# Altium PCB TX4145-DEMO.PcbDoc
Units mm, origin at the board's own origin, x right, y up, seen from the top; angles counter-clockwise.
Board outline 53.34 x 40.51 mm, 2 copper layers (Top Layer, Bottom Layer); 22 components, 10 nets, 62 pads, 65 vias.
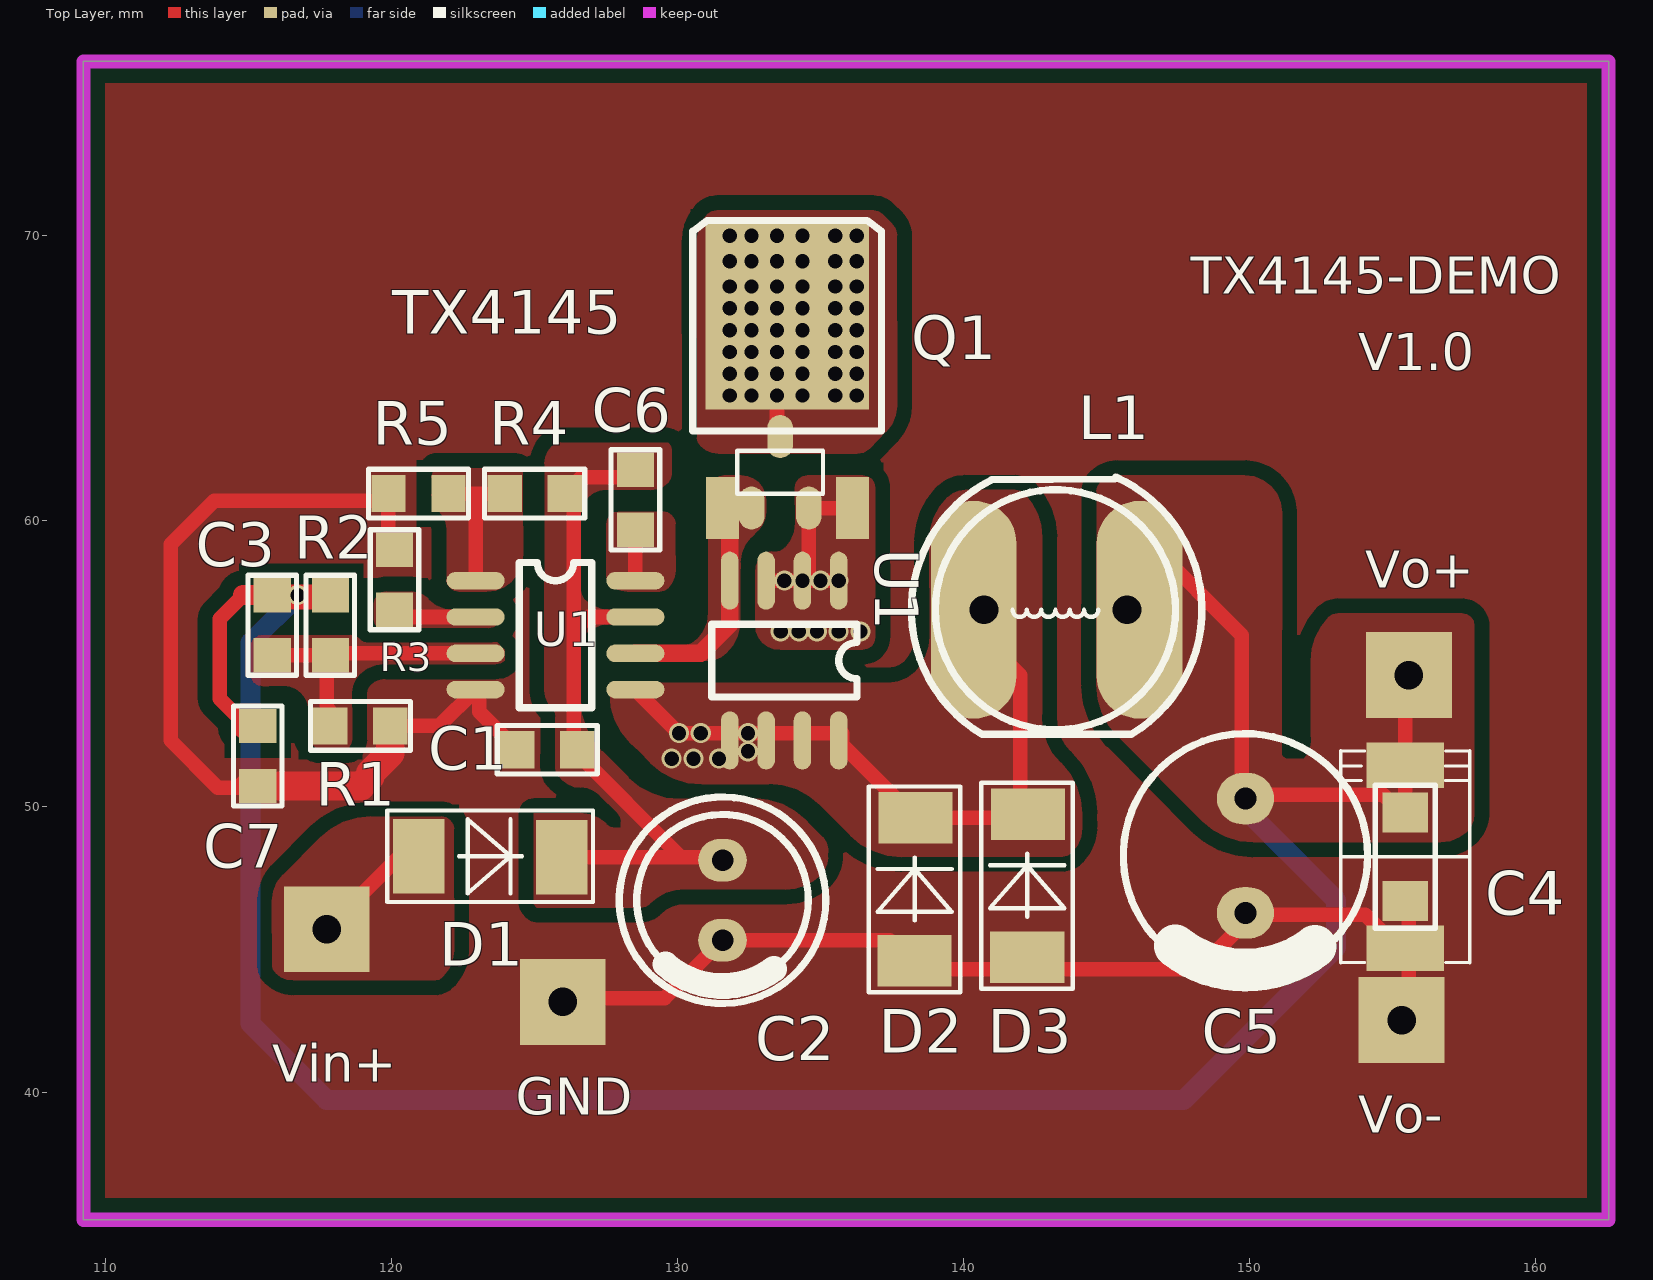
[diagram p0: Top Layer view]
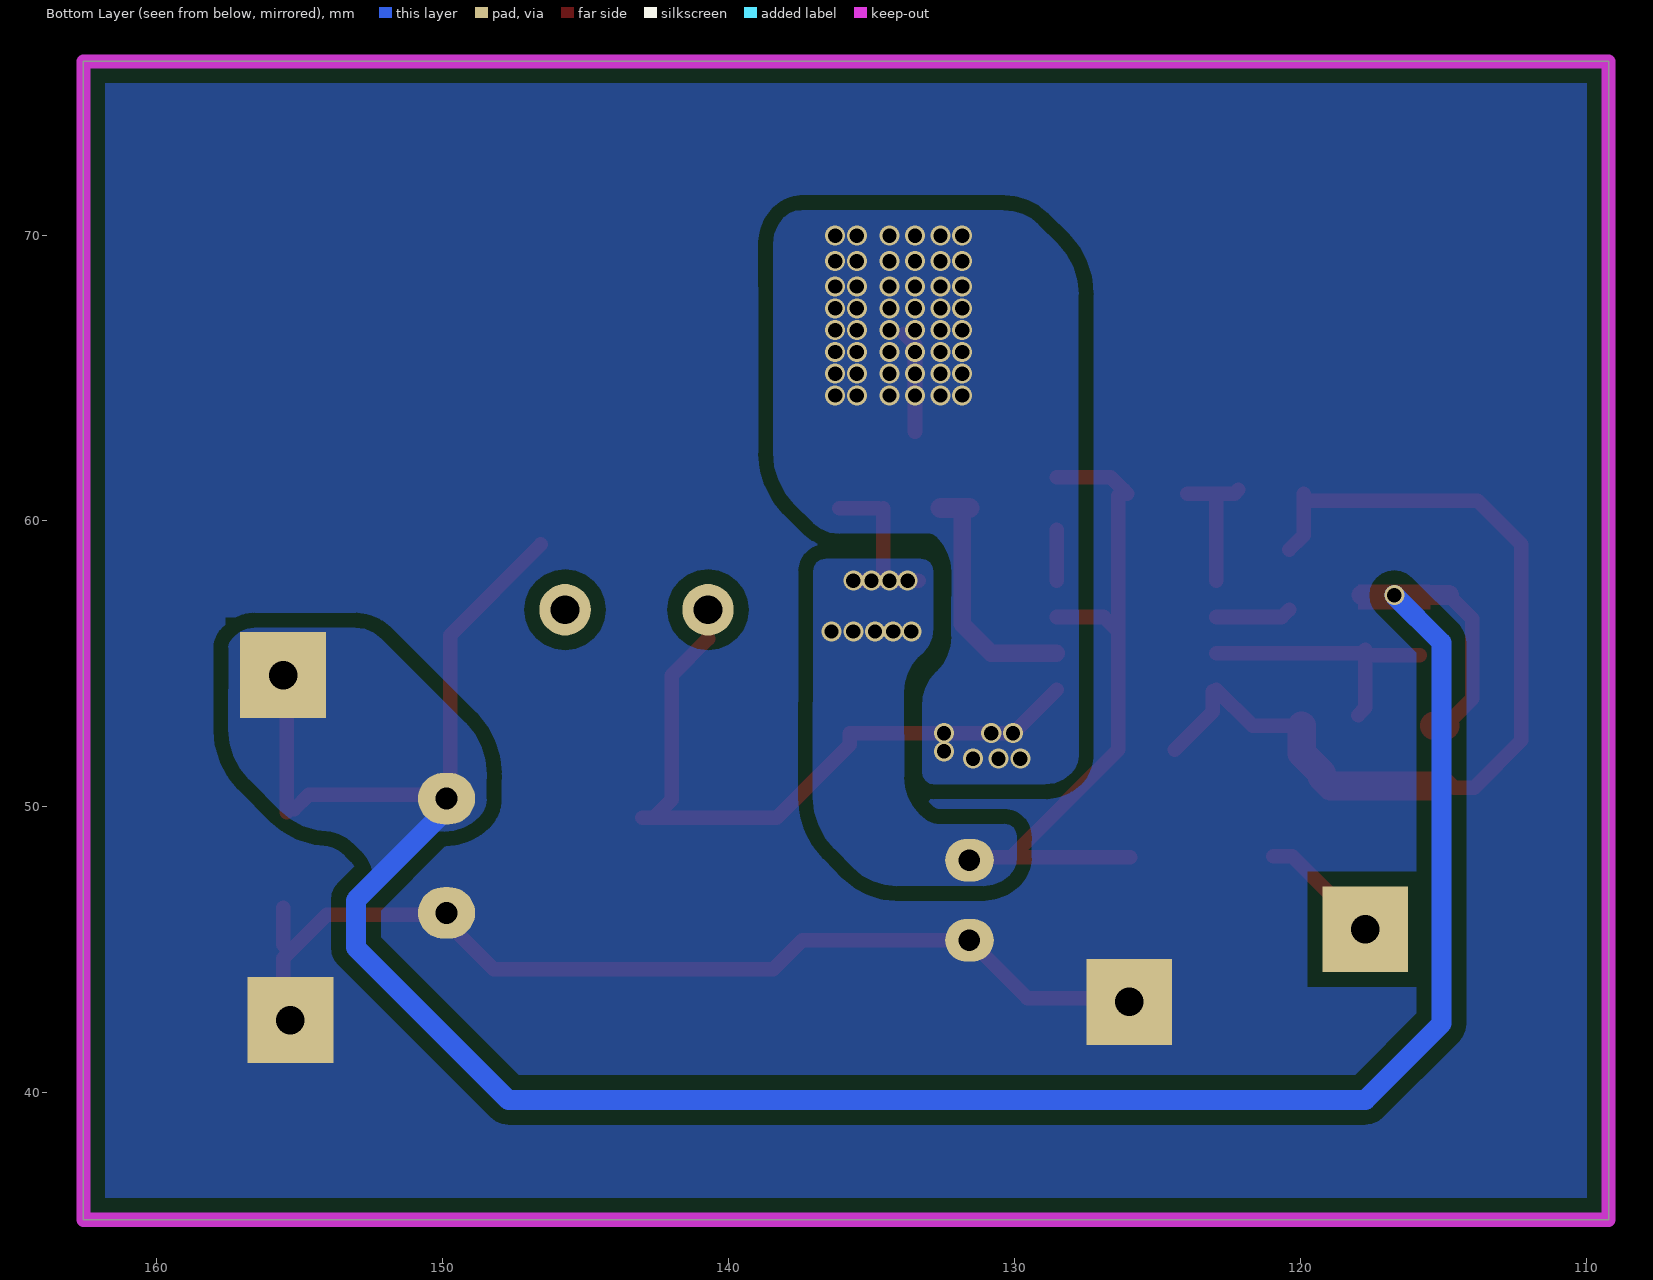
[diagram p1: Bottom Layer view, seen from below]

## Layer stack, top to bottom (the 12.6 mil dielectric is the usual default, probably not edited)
Top Layer: signal copper 0.0356
Dielectric: dielectric 0.32, FR-4, Dk 4.8
Bottom Layer: signal copper 0.0356

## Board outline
109.22,35.56 162.56,35.56 162.56,76.073 109.22,76.073

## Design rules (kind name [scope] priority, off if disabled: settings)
Clearance [All] p1: gap=0.508
ComponentClearance [All] p1 off: gap=0.254 collisioncheckmode=3 verticalgap=0.254 showdistances=FALSE
Height [All] p1 off: minheight=0 maxheight=25.4 prefheight=12.7
PlaneConnect [All] p1: planeconnectstyle=Direct reliefexpansion=0.508 reliefentries=4 reliefconductorwidth=0.254 reliefairgap=0.254
PolygonConnect [All] p1: connectstyle=Direct reliefconductorwidth=0.254 reliefentries=4 polygonreliefangle="90 Angle"
RoutingVias [All] p1: holewidth=0.711 width=1.27 viastyle="Through Hole" minholewidth=0.711 minwidth=1.27 maxholewidth=0.711 maxwidth=1.27
SilkscreenOverComponentPads SilkToSolderMaskClearance [IsPad] p1: minsilkscreentomaskgap=0.254
SolderMaskExpansion [All] p1: expansion=0.102
TestPointUsage [All] p1: valid=0 allowmultiple=FALSE
Testpoint [All] p1: side=3 testpointundercomponent=TRUE minsize=1.016 maxsize=2.54 preferedsize=1.524 minholesize=0 maxholesize=1.016 preferedholesize=0.813 testpointgrid=0.025 style=297 order=0123456789
Width [All] p1: maxlimit=5.08 minlimit=0.508 preferedwidth=0.508
20 further rules are at their usual default settings.

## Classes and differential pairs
component class OC5823-0902原理图: C1 C2 C3 C4 C5 C6 D1 D2 D3 L1 Q1 R1 R2 R3 R4 R5 U1

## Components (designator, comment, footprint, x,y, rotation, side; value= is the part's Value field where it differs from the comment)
C1 "CAP" 0805R 126.492,52 r180 top
C2 "" c6*12 131.572,46.736 r270 top
C3 "" 0805R 115.824,57.404 r270 top
C4 "" 1206R 155.448,48.26 r90 top
C5 "" C8*12 149.86,50.292 r180 top
C6 "" 0805R 128.524,59.69 r90 top
C7 "" 0805R 115.316,52.832 r270 top (schematic designator C4)
D1 "DIODE" SMB 123.444,48.26 r0 top
D2 "" SMB 138.303,47.117 r90 top
D3 "" SMB 142.24,47.244 r90 top
L1 "" CD105 143.256,56.896 r90 top
Q1 "MOSFET P" TO252 131.572,60.452 r0 top
R1 "" 0805R 117.856,57.404 r270 top
R2 "" 0805R 117.856,52.832 r0 top
R3 "" 0805R 120.1,56.896 r90 top
R4 "" 0805R 123.952,60.96 r0 top
R5 "" 0805R 119.888,60.96 r0 top
U1 "TX4145" SO-8 135.636,57.912 r270 top
U1 "TX4145" SO-8 122.936,57.912 r0 top
? "Comment" L8*10 140.716,56.896 r0 top
? "Comment" 7343 155.448,48.26 r0 top
? "Comment" SOT23-3 132.588,60.452 r0 top

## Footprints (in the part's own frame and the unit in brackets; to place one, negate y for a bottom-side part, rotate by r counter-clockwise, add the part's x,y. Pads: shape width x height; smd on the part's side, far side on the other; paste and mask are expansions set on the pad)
0805R [mm]
  rect 1.2x1.3 smd: 1(0,0) 2(2.1,0)
  silkscreen extent -0.7,-0.85 2.8,0.85
1206R [mm]
  rect 1.4x1.6 smd: 1(1.55,0) 2(-1.55,0)
  silkscreen extent -2.5,-1.05 2.5,1.05
7343 [mm]
  rect 2.7x1.6 smd: 1(0,3.2) 2(0,-3.2)
  silkscreen extent -2.25,-3.7 2.25,3.7
c6*12 [mm]
  oval 1.5x1.7 hole 0.75: 1(-1.4,0) 2(1.4,0)
  silkscreen extent -3.61,-3.61 3.61,3.61
C8*12 [mm]
  oval 2x1.8 hole 0.762: 1(0,0) 2(0,4)
  silkscreen extent -4.27,-2.27 4.27,6.27
CD105 [mm]
  oval 7.62x3 smd: 1(0,-2.9) 2(0,2.9)
  silkscreen extent -4.36,-5.08 4.64,5.08
L8*10 [mm]
  round 1.8 hole 1: 1(0,0) 2(5,0)
  silkscreen extent -1.7,-4.2 6.7,4.2
SMB [mm]
  rect 1.8x2.6 smd: 1(-2.5,0.016) 2(2.5,-0.016)
  silkscreen extent -3.6,-1.58 3.6,1.62
SO-8 [mil]
  oval 80x24 smd: 1(0,0) 2(0,-50) 3(0,-100) 4(0,-150) 5(220,-150) 6(220,-100) 7(220,-50) 8(220,0)
  silkscreen extent 60,-175 160,25
SOT23-3 [mm]
  oval 0.9x1.5 smd: 1(0,0) 2(1,2.5) 3(2,0)
  silkscreen extent -0.5,0.5 2.5,2
TO252 [mil]
  rect 45x85 smd: 1(0,0) 3(179,0)
  rect 225x255.91 smd: 2(89,263.78)
  silkscreen extent -41,106 219,396

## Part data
C1: "Capacitor"
C2 C5: library part CAPACITOR, "Capacitor"
C3 C4 C6 C7: library part CAP, "Capacitor"
D1: "Diode"
D2 D3: library part DIODE, "Diode"
L1: library part INDUCTOR
R1 R2 R3 R4 R5: library part RES1_1
U1: library part "HEADER 4X2"

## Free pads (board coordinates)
  rect 3x3 hole 1: 0(155.321,42.545) 1(155.575,54.61) 2(117.729,45.72) 3(125.984,43.18)

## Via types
v1: diameter 0.7, hole 0.5, Top Layer to Bottom Layer, 65 vias

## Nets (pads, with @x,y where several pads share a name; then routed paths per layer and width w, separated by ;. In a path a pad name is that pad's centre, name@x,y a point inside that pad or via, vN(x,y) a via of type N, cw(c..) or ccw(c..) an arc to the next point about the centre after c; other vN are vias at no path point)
GND: ?.2@155.448,45.06 C1.2 C2.2 C4.2 C5.2 C7.2 D2.1 D3.1 pad.0 pad.3 R2.2 R3.2 R5.1 U1.4@122.936,54.102 | length 69.3
  Top Layer w0.508: C7.2@115.443,50.732 C7.2 114.994,51.054 114.613,50.673 113.919,50.673 112.268,52.324 112.268,59.182 113.792,60.706 R5.1@119.888,60.706 ; R5.1 119.888,59.504 R3.2@120.396,58.996 ; R2.2 121.666,52.832 122.936,54.102 123.063,54.049 123.063,53.329 C1.2 ; pad.3@126.492,43.307 129.543,43.307 C2.2 137.417,45.336 138.43,44.323 148.209,44.323 150.114,46.228 154.051,46.228 155.575,44.704 155.575,42.799 pad.0 ; ?.2@155.448,45.06 155.575,45.187 C4.2@155.575,46.482
  Top Layer w1: C7.2 118.931,50.732 119.253,51.054 119.253,51.174 119.956,51.877 R2.2
NetC1_1: ?.3 C1.1 C2.1 C6.2 D1.2 Q1.3 R4.2 U1.1@135.636,57.912 U1.2@134.366,57.912 U1.3@133.096,57.912 U1.7@128.524,56.642 | length 31.3
  Top Layer w0.508: D1.2 131.464,48.244 C2.1 ; R4.2 126.628,61.536 C6.2@128.524,61.536 ; R4.2@126.166,61.074 126.365,60.875 126.365,52 130.121,48.244 ; 126.492,56.261 126.873,56.642 U1.7@128.524,56.642 ; U1.3@133.35,57.912 v1(135.636,57.912) ; v1(134.366,57.912) 134.588,58.134 ?.3 ; ?.3@134.747,60.452 Q1.3
  other v1: 133.604,56.134 134.239,56.134 134.874,56.134 135.636,56.134 136.398,56.134 133.731,57.912 135.001,57.912
NetC3_1: ?.1@155.448,51.46 ?.2@145.716,56.896 C3.1 C4.1 C5.1 C7.1 L1.1 pad.1 R1.1 | length 92.6
  Top Layer w0.508: 114.808,57.404 113.988,56.584 113.988,53.779 C7.1@114.935,52.832 ; L1.1@146.558,59.182 149.733,56.007 149.733,50.419 154.686,50.419 C4.1@155.194,49.911 ; C4.1 155.448,54.483 pad.1
  Top Layer w0.7: 114.808,57.404 R1.1
  Top Layer w1: C7.1@114.935,52.832 C7.1
  Bottom Layer w0.7: v1(116.713,57.404) 115.062,55.753 115.062,42.418 117.729,39.751 147.701,39.751 153.035,45.085 153.035,46.736 C5.1@149.733,50.038
NetC3_2: C3.2 R1.2 R2.1 U1.3@122.936,55.372 | length 9.7
  Top Layer w0.508: C3.2 117.788,55.304 R1.2@117.856,55.372 ; R2.1@117.983,53.213 117.729,53.467 117.729,55.499 R1.2@117.856,55.372 ; U1.3@122.936,55.372 R1.2@117.856,55.372
NetC6_1: C6.1 U1.8@128.524,57.912 | length 1.8
  Top Layer w0.508: U1.8@128.524,57.912 C6.1
NetD2_2: ?.1@140.716,56.896 ?.2@133.588,62.952 D2.2 D3.2 L1.2 Q1.2 U1.5 U1.6@133.096,52.324 U1.7@134.366,52.324 U1.8@135.636,52.324 | length 27.2
  Top Layer w0.508: U1.5@128.524,54.102 v1(130.048,52.578) 135.763,52.578 135.763,52.173 D2.2 D3.2@143.018,49.617 ; ?.2@133.477,63.119 133.477,66.167 Q1.2@133.858,66.548 ; L1.2@140.716,55.88 141.986,54.61 141.986,50.252 D3.2@142.621,49.617
  other v1: 129.794,51.689 130.556,51.689 131.445,51.689 132.461,51.943 130.81,52.578 132.461,52.578 131.826,64.389 132.588,64.389 133.477,64.389 134.366,64.389 135.509,64.389 136.271,64.389 131.826,65.151 132.588,65.151 133.477,65.151 134.366,65.151 135.509,65.151 136.271,65.151 131.826,65.913 132.588,65.913 133.477,65.913 134.366,65.913 135.509,65.913 136.271,65.913 131.826,66.675 132.588,66.675 133.477,66.675 134.366,66.675 135.509,66.675 136.271,66.675 131.826,67.437 132.588,67.437 133.477,67.437 134.366,67.437 135.509,67.437 136.271,67.437 131.826,68.199 132.588,68.199 133.477,68.199 134.366,68.199 135.509,68.199 136.271,68.199 131.826,69.088 132.588,69.088 133.477,69.088 134.366,69.088 135.509,69.088 136.271,69.088 131.826,69.977 132.588,69.977 133.477,69.977 134.366,69.977 135.509,69.977 136.271,69.977
NetOC5823_1: R4.1 R5.2 U1.1@122.936,57.912 | length 4.9
  Top Layer w0.508: R5.2@122.174,61.087 122.301,60.96 R4.1 ; U1.1@122.936,57.912 122.936,60.833 123.063,60.96
NetOC5823_2: R3.1 U1.2@122.936,56.642 | length 2.6
  Top Layer w0.508: R3.1@120.396,56.896 120.65,56.642 U1.2@122.936,56.642
NetOC5823_6: ?.1@132.588,60.452 Q1.1 U1.4@131.826,57.912 U1.6@128.524,55.372 | length 8.5
  Top Layer w0.6: U1.6@128.524,55.372 130.81,55.372 131.826,56.388 Q1.1@131.826,60.198
  Top Layer w0.7: Q1.1 ?.1@132.588,60.452
VCC: D1.1 pad.2 | length 4.3
  Top Layer w0.508: pad.2 120.285,48.276 D1.1

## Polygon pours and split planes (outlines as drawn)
GND on Top Layer "Top Layer-No Net" (solid, remove dead copper, pour order 1011): 109.22,35.306 161.027,35.306 ccw(c161.027,37.474) 162.56,35.941 162.56,74.847 ccw(c160.826,74.847) 162.052,76.073 110.446,76.073 ccw(c110.446,74.339) 109.22,75.565 109.22,35.56
NetD2_2 on Top Layer "Top Layer-No Net" (solid, remove dead copper, pour order 1010): 130.683,62.992 130.683,69.819 cw(c131.984,69.819) 131.064,70.739 cw(c131.371,70.432) 131.371,70.866 132.207,70.866 136.853,70.866 cw(c136.853,70.432) 137.16,70.739 137.488,70.411 cw(c137.055,69.977) 137.668,69.977 137.668,64.039 cw(c136.367,64.039) 137.287,63.119 136.705,62.537 cw(c136.271,62.97) 136.271,62.357 131.423,62.357 cw(c131.423,63.224) 130.81,62.611 cw(c131.117,62.918) 130.683,62.918 130.683,62.992
NetC3_2 on Top Layer "Top Layer-No Net" (solid, remove dead copper, pour order 1009): 123.698,55.753 119.179,55.753 cw(c119.179,56.187) 118.872,55.88 ccw(c118.565,55.573) 118.565,56.007 117.856,56.007 115.496,56.007 ccw(c115.496,55.573) 115.189,55.88 ccw(c115.496,55.573) 115.062,55.573 115.062,55.118 115.062,54.663 ccw(c115.496,54.663) 115.189,54.356 ccw(c115.496,54.663) 115.496,54.229 115.697,54.229 116.227,54.229 cw(c116.227,53.362) 116.84,53.975 cw(c116.227,53.362) 117.094,53.362 117.094,52.451 ccw(c117.401,52.451) 117.184,52.234 117.348,52.07 118.491,52.07 ccw(c118.184,52.377) 118.618,52.377 118.618,52.959 118.618,53.997 cw(c119.485,53.997) 118.872,54.61 cw(c119.792,53.69) 119.792,54.991 123.19,54.991 123.645,54.991 ccw(c123.645,55.425) 123.952,55.118 123.952,55.499 123.698,55.753
NetOC5823_2 on Top Layer "Top Layer-No Net" (solid, remove dead copper, pour order 1008): 123.571,56.896 122.205,56.896 cw(c122.205,58.197) 121.285,57.277 ccw(c120.672,56.664) 120.672,57.531 120.523,57.531 119.814,57.531 ccw(c119.814,57.097) 119.507,57.404 ccw(c119.814,57.097) 119.38,57.097 119.38,56.896 119.38,56.568 ccw(c119.814,56.568) 119.507,56.261 123.391,56.261 ccw(c123.391,56.695) 123.698,56.388 123.698,56.589 ccw(c123.264,56.589) 123.571,56.896
NetC3_1 on Top Layer "Top Layer-No Net" (solid, remove dead copper, pour order 1007): 144.653,59.944 144.653,54.265 ccw(c147.193,54.265) 145.397,52.469 145.415,52.451 148.354,49.512 ccw(c150.15,51.308) 150.15,48.768 153.289,48.768 156.687,48.768 ccw(c156.687,50.069) 157.607,49.149 ccw(c156.994,49.762) 157.861,49.762 157.861,52.197 157.861,56.335 ccw(c157.427,56.335) 157.734,56.642 ccw(c157.427,56.335) 157.427,56.769 156.591,56.769 153.088,56.769 ccw(c153.088,56.335) 152.781,56.642 ccw(c154.314,55.109) 152.146,55.109 152.146,52.578 152.146,52.302 cw(c151.279,52.302) 151.892,51.689 151.384,51.689 cw(c151.384,51.996) 151.167,51.779 151.13,51.816 151.13,52.07 151.13,60.294 ccw(c149.829,60.294) 150.749,61.214 ccw(c149.829,60.294) 149.829,61.595 146.939,61.595 145.393,61.595 ccw(c145.393,60.728) 144.78,61.341 ccw(c145.087,61.034) 144.653,61.034 144.653,60.325 144.653,59.69
NetOC5823_1 on Top Layer "Top Layer-No Net" (solid, remove dead copper, pour order 1006): 121.539,61.849 124.28,61.849 cw(c124.28,61.415) 124.587,61.722 124.587,60.833 124.587,58.832 cw(c123.286,58.832) 124.206,57.912 124.184,57.89 cw(c123.317,58.757) 123.317,57.531 122.354,57.531 cw(c122.354,57.965) 122.047,57.658 cw(c122.354,57.965) 121.92,57.965 121.92,58.674 121.92,59.712 ccw(c121.053,59.712) 121.666,60.325 cw(c122.279,60.938) 121.412,60.938 121.412,61.468 121.412,61.542 cw(c121.846,61.542) 121.539,61.849
NetC1_1 on Top Layer "Top Layer-No Net" (solid, remove dead copper, pour order 1005): 129.159,62.738 125.91,62.738 ccw(c125.91,62.304) 125.603,62.611 ccw(c126.216,61.998) 125.349,61.998 125.349,61.976 125.349,54.08 ccw(c126.216,54.08) 125.603,53.467 cw(c125.296,53.16) 125.73,53.16 125.73,52.324 125.73,51.361 ccw(c126.164,51.361) 125.857,51.054 125.969,50.942 ccw(c126.619,51.593) 126.619,50.673 cw(c126.619,49.753) 127.269,50.404 127.889,49.784 cw(c127.582,49.477) 128.016,49.477 128.016,49.276 127.815,49.276 cw(c127.815,49.71) 127.508,49.403 ccw(c126.588,48.483) 126.588,49.784 124.968,49.784 124.767,49.784 ccw(c124.767,49.35) 124.46,49.657 ccw(c125.073,49.044) 124.206,49.044 124.206,48.006 124.206,47.349 ccw(c125.073,47.349) 124.46,46.736 ccw(c125.073,47.349) 125.073,46.482 127.381,46.482 128.725,46.482 ccw(c128.725,46.916) 129.032,46.609 cw(c130.258,45.383) 130.258,47.117 132.08,47.117 133.775,47.117 ccw(c133.775,48.851) 135.001,47.625 ccw(c134.388,48.238) 135.255,48.238 135.255,48.514 ccw(c134.642,48.514) 135.075,48.948 134.62,49.403 134.475,49.548 ccw(c132.679,47.752) 132.679,50.292 130.937,50.292 130.084,50.292 cw(c130.084,52.832) 128.288,51.036 127.381,51.943 127.363,51.961 cw(c129.159,53.757) 126.619,53.757 126.619,54.229 126.619,55.7 cw(c127.053,55.7) 126.746,56.007 cw(c127.666,55.087) 127.666,56.388 127.889,56.388 128.927,56.388 ccw(c128.927,57.255) 129.54,56.642 129.466,56.716 ccw(c129.032,56.283) 129.032,56.896 127.666,56.896 cw(c127.666,58.197) 126.746,57.277 cw(c127.053,57.584) 126.619,57.584 126.619,57.912 126.619,60.22 cw(c127.486,60.22) 126.873,60.833 cw(c127.486,60.22) 127.486,61.087 128.27,61.087 129.054,61.087 ccw(c129.054,61.954) 129.667,61.341 ccw(c129.36,61.648) 129.794,61.648 129.794,62.103 129.794,62.484 ccw(c129.487,62.484) 129.704,62.701 129.667,62.738 129.159,62.738
NetC6_1 on Top Layer "Top Layer-No Net" (solid, remove dead copper, pour order 1004): 128.397,60.325 129.487,60.325 cw(c129.487,59.891) 129.794,60.198 cw(c129.487,59.891) 129.921,59.891 129.921,59.309 129.921,58.271 cw(c129.054,58.271) 129.667,57.658 cw(c129.36,57.965) 129.36,57.531 128.651,57.531 128.248,57.531 cw(c128.248,58.398) 127.635,57.785 cw(c127.942,58.092) 127.508,58.092 127.508,58.547 127.508,59.891 cw(c127.942,59.891) 127.635,60.198 cw(c127.942,59.891) 127.942,60.325 128.397,60.325
NetOC5823_6 on Top Layer "Top Layer-No Net" (solid, remove dead copper, pour order 1003): 128.397,55.626 130.07,55.626 ccw(c130.07,56.493) 130.683,55.88 ccw(c129.763,56.8) 131.064,56.8 131.064,58.674 131.064,60.855 cw(c131.931,60.855) 131.318,61.468 cw(c131.625,61.161) 131.625,61.595 131.826,61.595 132.229,61.595 cw(c132.229,60.728) 132.842,61.341 cw(c132.229,60.728) 133.096,60.728 133.096,60.325 cw(c132.176,60.325) 132.827,59.675 132.588,59.436 132.566,59.414 ccw(c133.433,58.547) 132.207,58.547 132.207,56.598 cw(c130.473,56.598) 131.699,55.372 cw(c131.086,55.985) 131.086,55.118 130.683,55.118 128.883,55.118 cw(c128.883,55.985) 128.27,55.372 cw(c128.577,55.372) 128.36,55.589 128.397,55.626
NetD2_2 on Top Layer "Top Layer-No Net" (solid, remove dead copper, pour order 1002): 128.778,54.356 137.383,54.356 ccw(c137.383,55.657) 138.303,54.737 ccw(c137.077,55.963) 138.811,55.963 138.811,56.007 138.811,59.3 cw(c140.979,59.3) 139.446,60.833 cw(c140.059,60.22) 140.059,61.087 140.081,61.087 141.806,61.087 cw(c141.806,60.653) 142.113,60.96 cw(c140.58,59.427) 142.748,59.427 142.748,53.34 142.748,53.095 ccw(c144.916,53.095) 143.383,51.562 143.401,51.544 cw(c141.605,49.748) 144.145,49.748 144.145,49.276 cw(c142.919,49.276) 143.786,48.409 143.764,48.387 cw(c143.457,48.694) 143.457,48.26 139.319,48.26 137.831,48.26 cw(c137.831,50.8) 136.035,49.004 136.017,49.022 134.983,50.056 ccw(c133.187,48.26) 133.187,50.8 131.318,50.8 130.846,50.8 cw(c130.846,53.34) 129.05,51.544 128.651,51.943 128.353,52.241 cw(c130.088,53.975) 127.635,53.975 cw(c127.942,53.975) 127.725,54.192 127.762,54.229 cw(c128.069,53.922) 128.069,54.356 128.778,54.356
NetC1_1 on Top Layer "Top Layer-No Net" (solid, remove dead copper, pour order 1001): 134.747,61.595 136.472,61.595 cw(c136.472,61.161) 136.779,61.468 cw(c136.472,61.161) 136.906,61.161 136.906,61.087 136.906,55.933 cw(c136.472,55.933) 136.779,55.626 cw(c136.472,55.933) 136.472,55.499 135.001,55.499 133.582,55.499 cw(c133.582,56.366) 132.969,55.753 cw(c133.582,56.366) 132.715,56.366 132.715,56.896 132.715,58.188 cw(c133.582,58.188) 132.969,58.801 cw(c133.276,58.494) 133.276,58.928 133.35,58.928 133.424,58.928 ccw(c133.424,59.362) 133.731,59.055 133.753,59.077 ccw(c132.886,59.944) 134.112,59.944 134.112,61.161 cw(c134.546,61.161) 134.239,61.468 cw(c134.546,61.161) 134.546,61.595 134.747,61.595
VCC on Top Layer "Top Layer-No Net" (solid, remove dead copper, pour order 1000): 120.396,49.657 121.74,49.657 cw(c121.74,49.223) 122.047,49.53 cw(c121.74,49.223) 122.174,49.223 122.174,48.641 122.174,44.989 cw(c120.873,44.989) 121.793,44.069 121.756,44.032 cw(c121.539,44.249) 121.539,43.942 116.564,43.942 cw(c116.564,44.809) 115.951,44.196 115.914,44.233 cw(c116.131,44.45) 115.824,44.45 115.824,46.705 cw(c117.125,46.705) 116.205,47.625 117.493,48.913 cw(c119.289,47.117) 119.289,49.657 120.396,49.657
GND on Bottom Layer "Top Layer-No Net" (solid, remove dead copper, pour order 1016): 109.22,35.56 161.64,35.56 ccw(c161.64,36.861) 162.56,35.941 162.56,76.073 110.446,76.073 ccw(c110.446,74.339) 109.22,75.565 109.22,35.56
NetC3_1 on Bottom Layer "Top Layer-No Net" (solid, remove dead copper, pour order 1015): 152.4,47.371 cw(c153.933,47.371) 152.849,48.455 153.035,48.641 153.074,48.68 cw(c154.267,47.486) 154.267,49.174 154.267,49.842 cw(c155.263,49.842) 154.559,50.546 ccw(c153.333,49.32) 153.333,51.054 149.606,51.054 ccw(c151.752,51.054) 150.235,49.536 150.921,48.85 152.446,47.325
NetC3_1 on Bottom Layer "Top Layer-No Net" (solid, remove dead copper, pour order 1014): 148.463,50.8 148.463,51.145 cw(c151.003,51.145) 149.207,52.941 152.146,55.88 cw(c153.066,54.96) 153.066,56.261 156.591,56.261 cw(c156.591,55.341) 157.241,55.992 157.353,55.88 cw(c157.046,55.573) 157.48,55.573 157.48,52.705 cw(c155.027,52.705) 156.762,50.971 156.718,50.927 155.684,49.893 cw(c153.888,51.689) 153.888,49.149 151.003,49.149 149.943,49.149 cw(c149.943,50.883) 148.717,49.657 cw(c149.33,50.27) 148.463,50.27 148.463,50.8
NetD2_2 on Bottom Layer "Top Layer-No Net" (solid, remove dead copper, pour order 1013): 133.223,51.435 133.223,53.511 ccw(c131.489,53.511) 132.715,54.737 cw(c133.941,55.963) 132.207,55.963 132.207,56.515 132.207,58.21 cw(c133.941,58.21) 132.715,59.436 cw(c133.022,59.129) 133.022,59.563 135.382,59.563 136.113,59.563 ccw(c136.113,60.864) 137.033,59.944 137.686,60.597 ccw(c135.89,62.393) 138.43,62.393 138.43,66.675 138.43,69.692 ccw(c137.129,69.692) 138.049,70.612 ccw(c137.436,69.999) 137.436,70.866 136.525,70.866 130.385,70.866 ccw(c130.385,69.132) 129.159,70.358 128.506,69.705 ccw(c130.302,67.909) 127.762,67.909 127.762,61.976 127.762,51.794 ccw(c128.629,51.794) 128.016,51.181 ccw(c128.936,52.101) 128.936,50.8 129.413,50.8 132.842,50.8 ccw(c132.842,51.107) 133.059,50.89 133.096,50.927 ccw(c132.789,51.234) 133.223,51.234 133.223,51.435
NetC1_1 on Bottom Layer "Top Layer-No Net" (solid, remove dead copper, pour order 1012): 130.429,49.403 132.61,49.403 ccw(c132.61,50.27) 133.223,49.657 133.319,49.753 ccw(c132.018,51.054) 133.858,51.054 133.858,54.019 ccw(c132.124,54.019) 133.35,55.245 133.201,55.394 cw(c134.068,56.261) 132.842,56.261 132.842,58.24 cw(c133.276,58.24) 132.969,58.547 cw(c133.276,58.24) 133.276,58.674 133.731,58.674 136.599,58.674 cw(c136.599,58.24) 136.906,58.547 cw(c136.599,58.24) 137.033,58.24 137.033,57.023 137.033,50.328 cw(c134.493,50.328) 136.289,48.532 135.636,47.879 cw(c134.103,49.412) 134.103,47.244 131.572,47.244 131.095,47.244 cw(c131.095,48.545) 130.175,47.625 cw(c130.788,48.238) 129.921,48.238 129.921,48.641 129.921,48.969 cw(c130.355,48.969) 130.048,49.276 cw(c130.355,48.969) 130.355,49.403 130.429,49.403

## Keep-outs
Keep-Out Layer:
  the board outline again, w0.5

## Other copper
Top Layer:
  rectangle net NetC3_1: 115.443,56.896 117.983,57.785

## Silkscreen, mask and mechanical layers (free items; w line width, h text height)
Top Overlay:
  text "TX4145-DEMO" at 147.955,67.945 h1.3
  text "V1.0" at 153.797,65.278 h1.3
  text "Vo+" at 154.051,57.658 h1.3
  text "Vin+" at 115.824,40.386 h1.3
  text "GND" at 124.333,39.243 h1.3
  text "Vo-" at 153.797,38.608 h1.3
Bottom Solder:
  region: 129.921,70.231 128.734,69.044 ccw(c130.469,67.31) 128.016,67.31 128.016,52.995 ccw(c130.556,52.995) 128.76,51.199 128.778,51.181 ccw(c129.085,51.488) 129.085,51.054 131.953,51.054 ccw(c131.953,52.28) 132.82,51.413 132.842,51.435 ccw(c132.535,51.742) 132.969,51.742 132.969,53.467 ccw(c132.049,53.467) 132.7,54.117 131.953,54.864 cw(c132.566,55.477) 131.699,55.477 131.699,57.876 cw(c134.239,57.876) 132.443,59.672 132.461,59.69 cw(c133.074,59.077) 133.074,59.944 135.382,59.944 ccw(c135.382,62.397) 137.116,60.662 138.049,61.595 138.049,69.005 ccw(c136.315,69.005) 137.541,70.231 ccw(c137.234,69.924) 137.234,70.358 130.228,70.358 ccw(c130.228,69.924)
